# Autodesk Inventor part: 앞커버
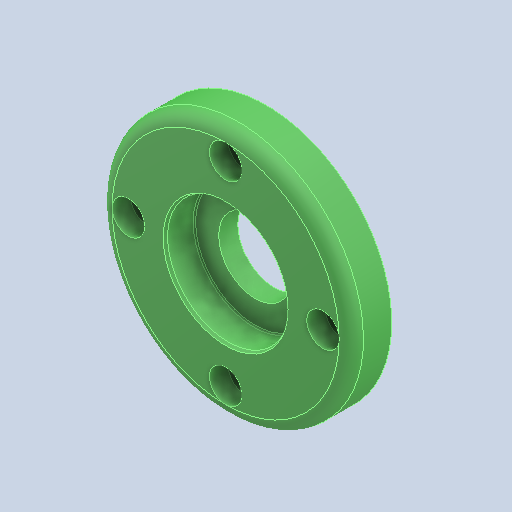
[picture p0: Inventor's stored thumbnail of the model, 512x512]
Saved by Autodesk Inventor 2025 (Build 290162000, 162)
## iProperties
Created: 2024-07
Part Number: 앞커버
Material: 알루미늄 6061
Document SubType Name: Modeling
Designer: Administrator
Density: 2.71 g/cm^3
Appearance: 기본값
Author: jhkim
Sending System: Autodesk Inventor 2025
Preprocessor: ST-DEVELOPER v20
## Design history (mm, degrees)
feature "솔리드1"
node "솔리드2"
